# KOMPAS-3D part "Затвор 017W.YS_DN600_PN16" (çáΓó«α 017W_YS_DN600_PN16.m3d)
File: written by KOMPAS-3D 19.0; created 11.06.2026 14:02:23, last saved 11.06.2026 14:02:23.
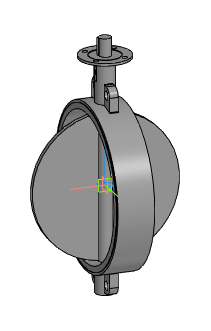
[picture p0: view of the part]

Document properties: Автор: Евгений; Полное имя файла: Z:\3.Личные\kachalov\001_3d для проектировщиков\x.x Тип 017W.Y(S) Затвор дисковый поворотный межфланцевый\_stp_Затвор 017W.YS_DN32-DN1200\Затвор 017W_YS_DN600_PN16.m3d

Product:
- Part/product: Затвор 017W.YS_DN600_PN16

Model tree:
1. Операция без истории:1  (labels: Затвор 017W.YS_DN600_PN16)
